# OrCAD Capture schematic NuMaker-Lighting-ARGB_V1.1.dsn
size Custom; title: NuMaker-Lighting-ARGB; rev: v1.0; note: NuMaker-Lighting-ARGB_V1.1
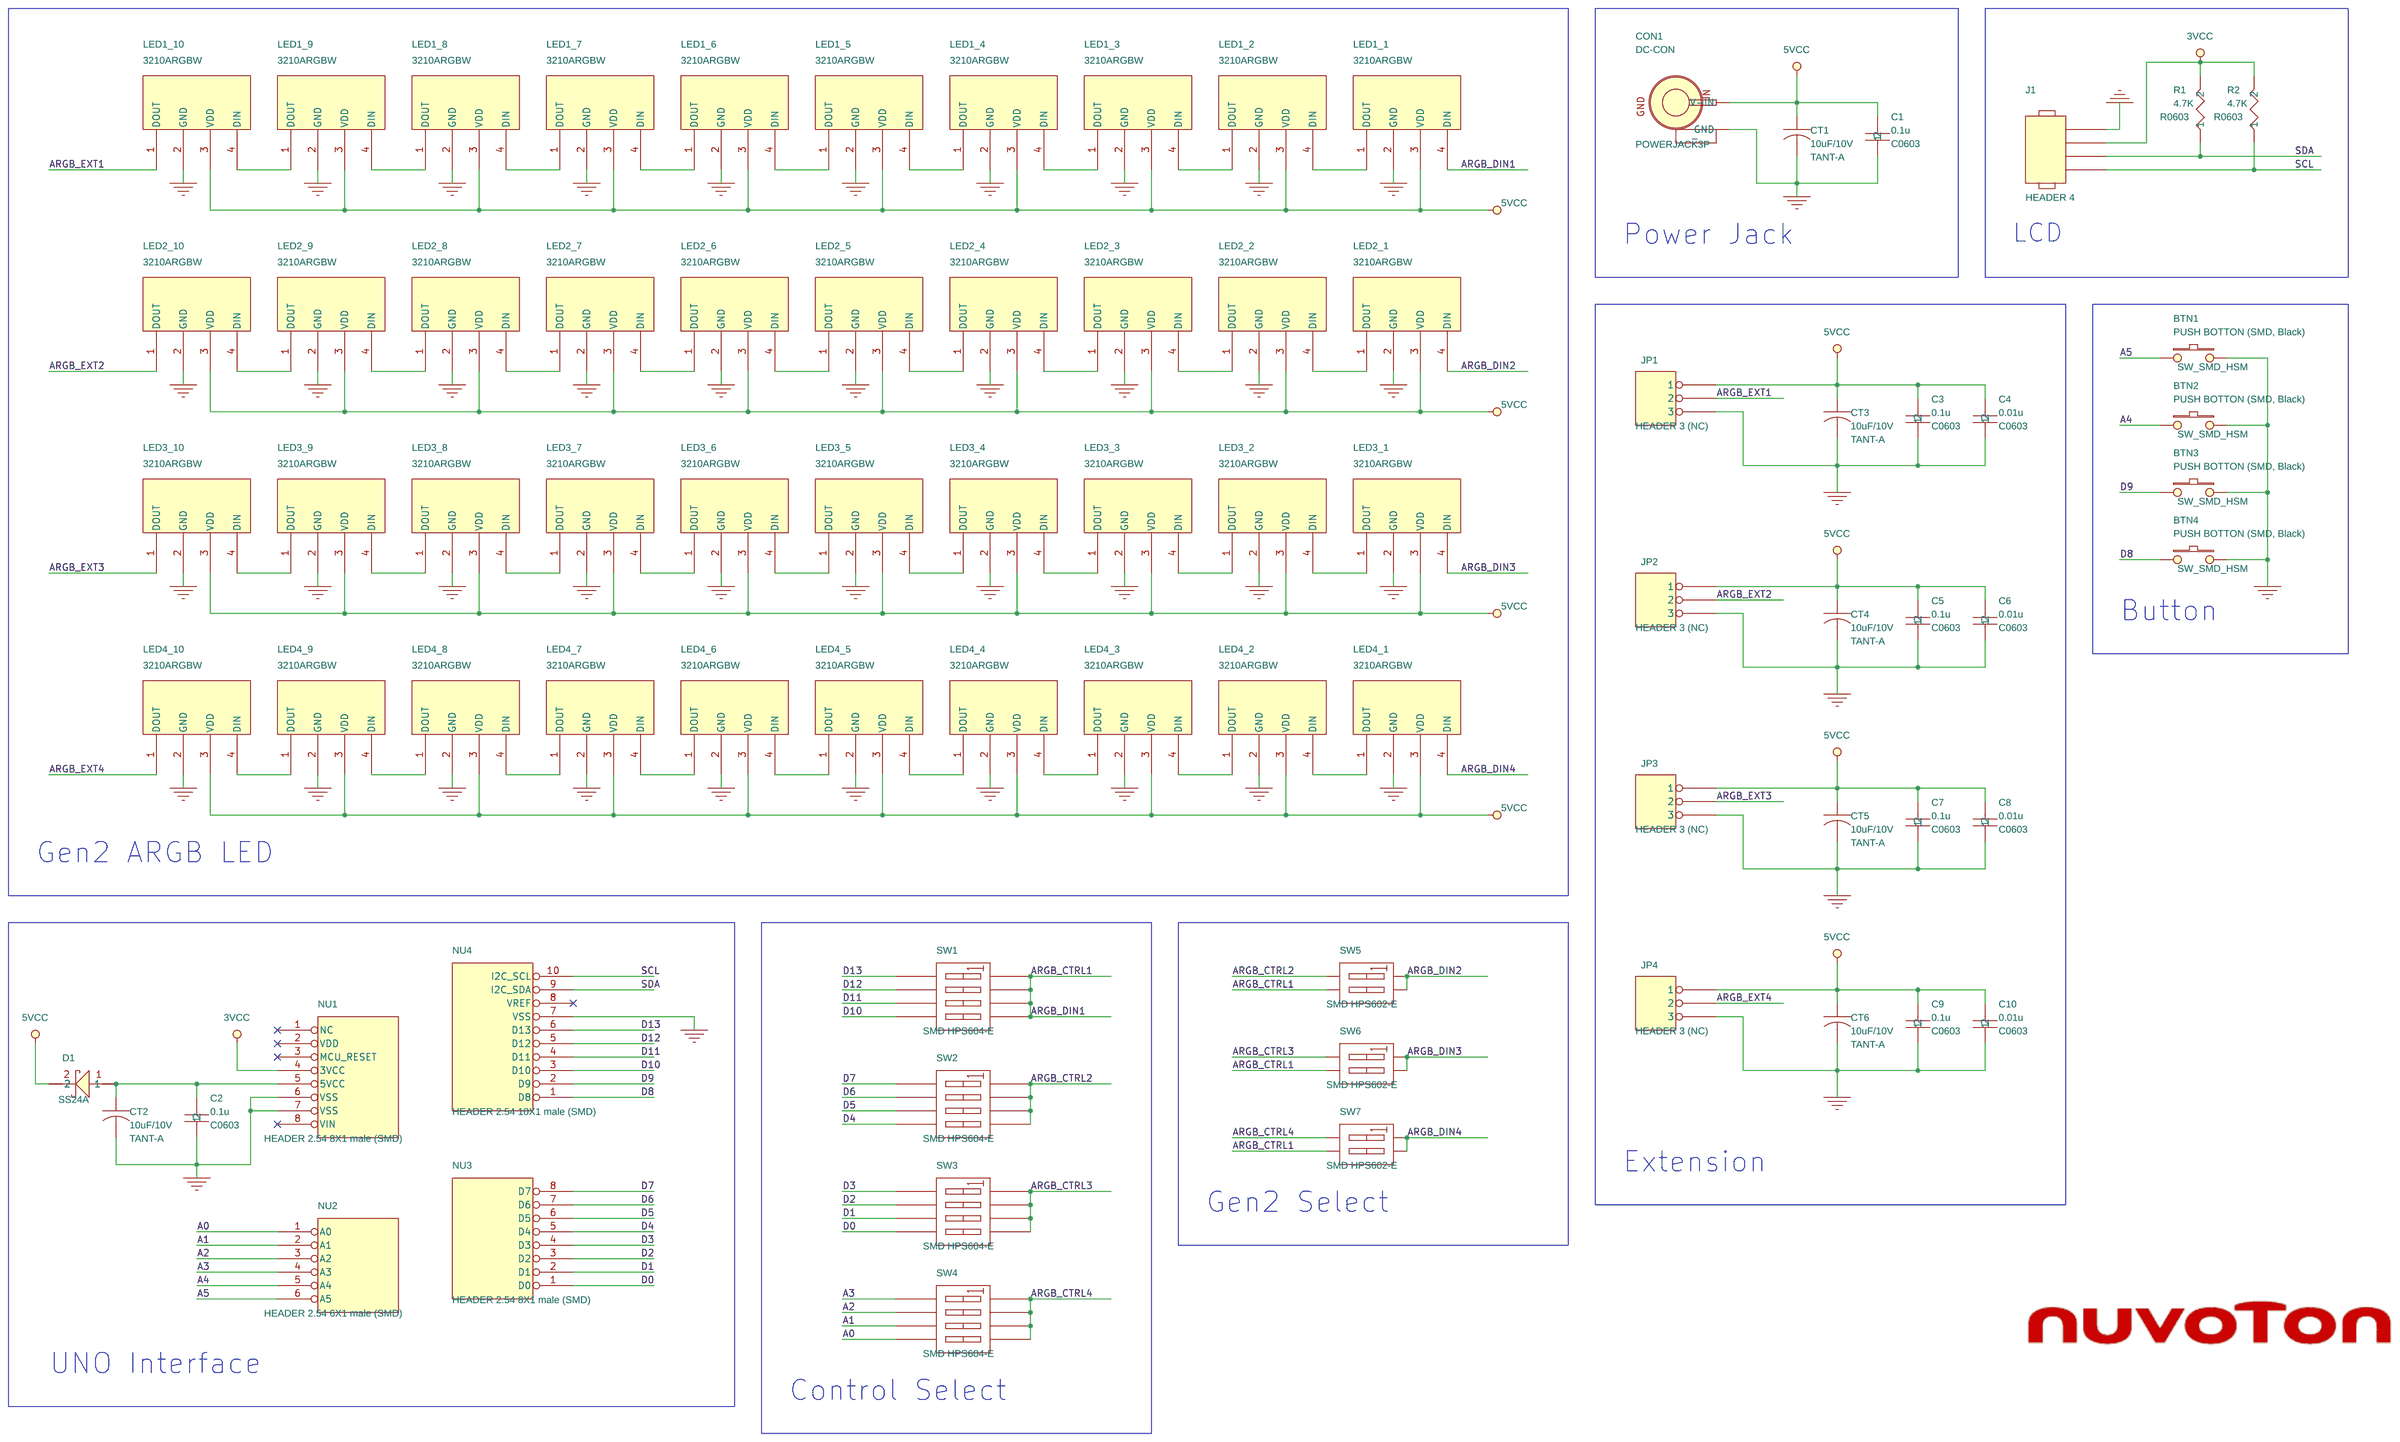
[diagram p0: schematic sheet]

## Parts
BTN1  PUSH BOTTON (SMD, Black)  [SW_SMD_HSM]
BTN2  PUSH BOTTON (SMD, Black)  [SW_SMD_HSM]
BTN3  PUSH BOTTON (SMD, Black)  [SW_SMD_HSM]
BTN4  PUSH BOTTON (SMD, Black)  [SW_SMD_HSM]
C1  0.1u  [C0603]
C2  0.1u  [C0603]
C3  0.1u  [C0603]
C4  0.01u  [C0603]
C5  0.1u  [C0603]
C6  0.01u  [C0603]
C7  0.1u  [C0603]
C8  0.01u  [C0603]
C9  0.1u  [C0603]
C10  0.01u  [C0603]
CON1  DC-CON  [POWERJACK\3P]
CT1  10uF/10V  [TANT-A]
CT2  10uF/10V  [TANT-A]
CT3  10uF/10V  [TANT-A]
CT4  10uF/10V  [TANT-A]
CT5  10uF/10V  [TANT-A]
CT6  10uF/10V  [TANT-A]
D1  SS24A  [RB060L]
J1  HEADER 4  [4PIN_I2C_LCD]
JP1  HEADER 3 (NC)  [HEADER1X3]
JP2  HEADER 3 (NC)  [HEADER1X3]
JP3  HEADER 3 (NC)  [HEADER1X3]
JP4  HEADER 3 (NC)  [HEADER1X3]
LED1_1  3210ARGBW  [3210ARGBW_L]
LED1_2  3210ARGBW  [3210ARGBW_L]
LED1_3  3210ARGBW  [3210ARGBW_L]
LED1_4  3210ARGBW  [3210ARGBW_L]
LED1_5  3210ARGBW  [3210ARGBW_L]
LED1_6  3210ARGBW  [3210ARGBW_L]
LED1_7  3210ARGBW  [3210ARGBW_L]
LED1_8  3210ARGBW  [3210ARGBW_L]
LED1_9  3210ARGBW  [3210ARGBW_L]
LED1_10  3210ARGBW  [3210ARGBW_L]
LED2_1  3210ARGBW  [3210ARGBW_L]
LED2_2  3210ARGBW  [3210ARGBW_L]
LED2_3  3210ARGBW  [3210ARGBW_L]
LED2_4  3210ARGBW  [3210ARGBW_L]
LED2_5  3210ARGBW  [3210ARGBW_L]
LED2_6  3210ARGBW  [3210ARGBW_L]
LED2_7  3210ARGBW  [3210ARGBW_L]
LED2_8  3210ARGBW  [3210ARGBW_L]
LED2_9  3210ARGBW  [3210ARGBW_L]
LED2_10  3210ARGBW  [3210ARGBW_L]
LED3_1  3210ARGBW  [3210ARGBW_L]
LED3_2  3210ARGBW  [3210ARGBW_L]
LED3_3  3210ARGBW  [3210ARGBW_L]
LED3_4  3210ARGBW  [3210ARGBW_L]
LED3_5  3210ARGBW  [3210ARGBW_L]
LED3_6  3210ARGBW  [3210ARGBW_L]
LED3_7  3210ARGBW  [3210ARGBW_L]
LED3_8  3210ARGBW  [3210ARGBW_L]
LED3_9  3210ARGBW  [3210ARGBW_L]
LED3_10  3210ARGBW  [3210ARGBW_L]
LED4_1  3210ARGBW  [3210ARGBW_L]
LED4_2  3210ARGBW  [3210ARGBW_L]
LED4_3  3210ARGBW  [3210ARGBW_L]
LED4_4  3210ARGBW  [3210ARGBW_L]
LED4_5  3210ARGBW  [3210ARGBW_L]
LED4_6  3210ARGBW  [3210ARGBW_L]
LED4_7  3210ARGBW  [3210ARGBW_L]
LED4_8  3210ARGBW  [3210ARGBW_L]
LED4_9  3210ARGBW  [3210ARGBW_L]
LED4_10  3210ARGBW  [3210ARGBW_L]
NU1  HEADER 2.54 8X1 male (SMD)  [SMD-1X8P-B]
NU2  HEADER 2.54 6X1 male (SMD)  [SMD-1X6P-B]
NU3  HEADER 2.54 8X1 male (SMD)  [SMD-1X8P-B]
NU4  HEADER 2.54 10X1 male (SMD)  [SMD-1X10P-B]
R1  4.7K  [R0603]
R2  4.7K  [R0603]
SW1  SMD HPS604-E  [SW1X4]
SW2  SMD HPS604-E  [SW1X4]
SW3  SMD HPS604-E  [SW1X4]
SW4  SMD HPS604-E  [SW1X4]
SW5  SMD HPS602-E  [SW1X2]
SW6  SMD HPS602-E  [SW1X2]
SW7  SMD HPS602-E  [SW1X2]

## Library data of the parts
BTN1-BTN4 = SW_PUSHBUTTON: Package: SMD PUSH BOTTOM
C1 = CAP-C_5: Package: 0603; element_no: C0004
C2 = CAP-C_9: Package: 0603; element_no: C0004
C3 = CAP-C_2: Package: 0603; element_no: C0004
C4 = CAP-C_8: Package: 0603; element_no: C0004
C5 = CAP-C_6: Package: 0603; element_no: C0004
C6 = CAP-C_7: Package: 0603; element_no: C0004
C7 = CAP-C_4: Package: 0603; element_no: C0004
C8 = CAP-C_3: Package: 0603; element_no: C0004
C9 = CAP-C_1: Package: 0603; element_no: C0004
C10 = CAP-C: Package: 0603; element_no: C0004
CON1 = DC-CON
CT1-CT6 = C_10uF_10V
D1 = D_SS24A
J1 = I2C_LCD_HEADER4
JP1 = HEADER_3_3
JP2 = HEADER_3_2
JP3 = HEADER_3_1
JP4 = HEADER_3
LED1_1-LED1_10 LED2_1-LED2_10 LED3_1-LED3_10 LED4_1-LED4_10 = 3210ARGBW
NU1 = POWER_CONNECT_0
NU2 = ADC_CONNECT_0
NU3 = PWM0_CONNECT_0
NU4 = PWM1_CONNECT_1
R1 = R_0_1: Package: 0603
R2 = R_0: Package: 0603
SW1-SW4 = SW_DIP-4_SM
SW5-SW7 = SW_DIP-4_2

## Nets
3VCC: J1.2 NU1.4(3VCC) R1.2 R2.2
5VCC: C1.2 C3.2 C4.2 C5.2 C6.2 C7.2 C8.2 C9.2 C10.2 CON1.1(V-IN) CT1.1 CT3.1 CT4.1 CT5.1 CT6.1 D1.2 JP1.1 JP2.1 JP3.1 JP4.1 LED1_1.3(VDD) LED1_2.3(VDD) LED1_3.3(VDD) LED1_4.3(VDD) LED1_5.3(VDD) LED1_6.3(VDD) LED1_7.3(VDD) LED1_8.3(VDD) LED1_9.3(VDD) LED1_10.3(VDD) LED2_1.3(VDD) LED2_2.3(VDD) LED2_3.3(VDD) LED2_4.3(VDD) LED2_5.3(VDD) LED2_6.3(VDD) LED2_7.3(VDD) LED2_8.3(VDD) LED2_9.3(VDD) LED2_10.3(VDD) LED3_1.3(VDD) LED3_2.3(VDD) LED3_3.3(VDD) LED3_4.3(VDD) LED3_5.3(VDD) LED3_6.3(VDD) LED3_7.3(VDD) LED3_8.3(VDD) LED3_9.3(VDD) LED3_10.3(VDD) LED4_1.3(VDD) LED4_2.3(VDD) LED4_3.3(VDD) LED4_4.3(VDD) LED4_5.3(VDD) LED4_6.3(VDD) LED4_7.3(VDD) LED4_8.3(VDD) LED4_9.3(VDD) LED4_10.3(VDD)
GND: BTN1.2 BTN2.2 BTN3.2 BTN4.2 C1.1 C2.1 C3.1 C4.1 C5.1 C6.1 C7.1 C8.1 C9.1 C10.1 CON1.2(GND) CT1.2 CT2.2 CT3.2 CT4.2 CT5.2 CT6.2 J1.1 JP1.3 JP2.3 JP3.3 JP4.3 LED1_1.2(GND) LED1_2.2(GND) LED1_3.2(GND) LED1_4.2(GND) LED1_5.2(GND) LED1_6.2(GND) LED1_7.2(GND) LED1_8.2(GND) LED1_9.2(GND) LED1_10.2(GND) LED2_1.2(GND) LED2_2.2(GND) LED2_3.2(GND) LED2_4.2(GND) LED2_5.2(GND) LED2_6.2(GND) LED2_7.2(GND) LED2_8.2(GND) LED2_9.2(GND) LED2_10.2(GND) LED3_1.2(GND) LED3_2.2(GND) LED3_3.2(GND) LED3_4.2(GND) LED3_5.2(GND) LED3_6.2(GND) LED3_7.2(GND) LED3_8.2(GND) LED3_9.2(GND) LED3_10.2(GND) LED4_1.2(GND) LED4_2.2(GND) LED4_3.2(GND) LED4_4.2(GND) LED4_5.2(GND) LED4_6.2(GND) LED4_7.2(GND) LED4_8.2(GND) LED4_9.2(GND) LED4_10.2(GND) NU1.6(VSS) NU1.7(VSS) NU4.7(VSS)
A0: NU2.1(A0) SW4.4(A4)
A1: NU2.2(A1) SW4.3(A3)
A2: NU2.3(A2) SW4.2(A2)
A3: NU2.4(A3) SW4.1(A1)
A4: BTN2.1 NU2.5(A4)
A5: BTN1.1 NU2.6(A5)
ARGB_CTRL1: LED1_1.4(DIN) SW1.5(B4) SW1.6(B3) SW1.7(B2) SW1.8(B1) SW5.2(A2) SW6.2(A2) SW7.2(A2)
ARGB_CTRL2: SW2.5(B4) SW2.6(B3) SW2.7(B2) SW2.8(B1) SW5.1(A1)
ARGB_CTRL3: SW3.5(B4) SW3.6(B3) SW3.7(B2) SW3.8(B1) SW6.1(A1)
ARGB_CTRL4: SW4.5(B4) SW4.6(B3) SW4.7(B2) SW4.8(B1) SW7.1(A1)
ARGB_DIN2: LED2_1.4(DIN) SW5.3(B1) SW5.4(B2)
ARGB_DIN3: LED3_1.4(DIN) SW6.3(B1) SW6.4(B2)
ARGB_DIN4: LED4_1.4(DIN) SW7.3(B1) SW7.4(B2)
ARGB_EXT1: JP1.2 LED1_10.1(DOUT)
ARGB_EXT2: JP2.2 LED2_10.1(DOUT)
ARGB_EXT3: JP3.2 LED3_10.1(DOUT)
ARGB_EXT4: JP4.2 LED4_10.1(DOUT)
D0: NU3.1(D0) SW3.4(A4)
D1: NU3.2(D1) SW3.3(A3)
D2: NU3.3(D2) SW3.2(A2)
D3: NU3.4(D3) SW3.1(A1)
D4: NU3.5(D4) SW2.4(A4)
D5: NU3.6(D5) SW2.3(A3)
D6: NU3.7(D6) SW2.2(A2)
D7: NU3.8(D7) SW2.1(A1)
D8: BTN4.1 NU4.1(D8)
D9: BTN3.1 NU4.2(D9)
D10: NU4.3(D10) SW1.4(A4)
D11: NU4.4(D11) SW1.3(A3)
D12: NU4.5(D12) SW1.2(A2)
D13: NU4.6(D13) SW1.1(A1)
SCL: J1.4 NU4.10(I2C_SCL) R2.1
SDA: J1.3 NU4.9(I2C_SDA) R1.1
N16780228: C2.2 CT2.1 D1.1 NU1.5(5VCC)
N16788873: LED1_1.1(DOUT) LED1_2.4(DIN)
N16791070: LED1_2.1(DOUT) LED1_3.4(DIN)
N16791292: LED1_3.1(DOUT) LED1_4.4(DIN)
N16791518: LED1_4.1(DOUT) LED1_5.4(DIN)
N16791745: LED1_5.1(DOUT) LED1_6.4(DIN)
N16791976: LED1_6.1(DOUT) LED1_7.4(DIN)
N16792210: LED1_7.1(DOUT) LED1_8.4(DIN)
N16792447: LED1_8.1(DOUT) LED1_9.4(DIN)
N16792687: LED1_9.1(DOUT) LED1_10.4(DIN)
N16794300: LED2_1.1(DOUT) LED2_2.4(DIN)
N16795137: LED2_2.1(DOUT) LED2_3.4(DIN)
N16795425: LED2_3.1(DOUT) LED2_4.4(DIN)
N16795584: LED2_4.1(DOUT) LED2_5.4(DIN)
N16795744: LED2_5.1(DOUT) LED2_6.4(DIN)
N16795905: LED2_6.1(DOUT) LED2_7.4(DIN)
N16796067: LED2_7.1(DOUT) LED2_8.4(DIN)
N16796230: LED2_8.1(DOUT) LED2_9.4(DIN)
N16796412: LED2_9.1(DOUT) LED2_10.4(DIN)
N16797911: LED3_1.1(DOUT) LED3_2.4(DIN)
N16798988: LED3_2.1(DOUT) LED3_3.4(DIN)
N16799155: LED3_3.1(DOUT) LED3_4.4(DIN)
N16799324: LED3_4.1(DOUT) LED3_5.4(DIN)
N16799494: LED3_5.1(DOUT) LED3_6.4(DIN)
N16799665: LED3_6.1(DOUT) LED3_7.4(DIN)
N16799837: LED3_7.1(DOUT) LED3_8.4(DIN)
N16800010: LED3_8.1(DOUT) LED3_9.4(DIN)
N16800184: LED3_9.1(DOUT) LED3_10.4(DIN)
N16800918: LED4_1.1(DOUT) LED4_2.4(DIN)
N16801793: LED4_2.1(DOUT) LED4_3.4(DIN)
N16801970: LED4_3.1(DOUT) LED4_4.4(DIN)
N16802148: LED4_4.1(DOUT) LED4_5.4(DIN)
N16802327: LED4_5.1(DOUT) LED4_6.4(DIN)
N16802507: LED4_6.1(DOUT) LED4_7.4(DIN)
N16802688: LED4_7.1(DOUT) LED4_8.4(DIN)
N16802870: LED4_8.1(DOUT) LED4_9.4(DIN)
N16803053: LED4_9.1(DOUT) LED4_10.4(DIN)

Not connected (* = marked no-connect by the designer): NU1 1(NC)* 2(VDD)* 3(MCU_RESET)* 8(VIN)*; NU4 8(VREF)*

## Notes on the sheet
- Power Jack
- LCD
- Button
- Gen2 ARGB LED
- Extension
- Gen2 Select
- UNO Interface
- Control Select
